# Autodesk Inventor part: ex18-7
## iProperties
Author: Elise Moss
Revision Number: A
Created: 2001-09
Part Number: ex18-7
Description: PLATE, RETAINING
Document SubType Name: Modeling
Designer: Elise Moss
Control State: 0
Master: False
Checked Out: False
PropertySet Name: Design Tracking Control
Length Units: 11272
Angle Units: 11279
Time Units: 11290
Mass Units: 11286
Shininess: 3
Angle Display Precision: 2
Document Length Units: 11272
Document Angle Units: 11286
Document Time Units: 11279
Document Mass Units: 11290
Document Length Units Precision: 3
Document Angle Units Precision: 0
Compacted: False
PropertySet Name: _Private Model Information
Density: 0.0
Volumn: 0.0
Area: 0.0
PropertySet Name: Model Information
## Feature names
1. Extrusion1
2. Hole1
